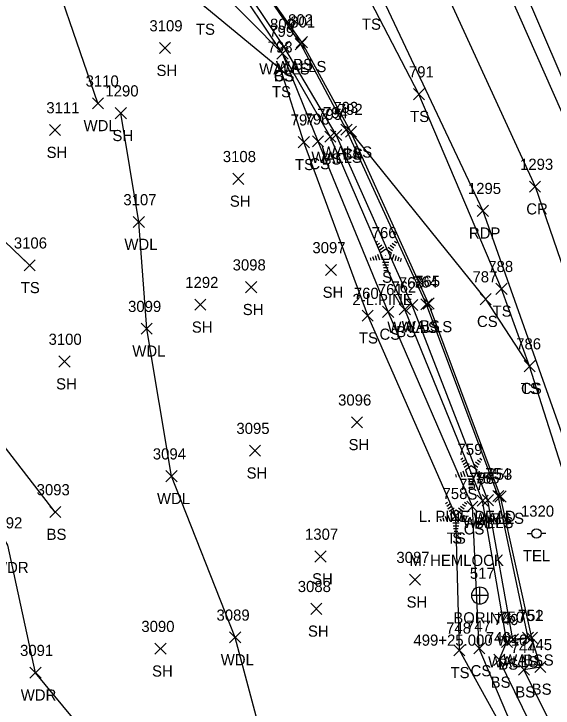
# Model space of a CAD drawing. Extents: x 1509053 to 1511576, y 400838 to 402572.
# Drawn here: x 1509663.6 to 1509760.3, y 401714.2 to 401838.7 of the extents above; entities that cross this region are included whole.
import ezdxf

# ---------------------------------------------------------------- set-up
doc = ezdxf.new("R2010")
doc.units = 0
for name, color, linetype in [('G_A', 7, 'Continuous'), ('G_C', 7, 'Continuous'), ('G_I', 7, 'Continuous'), ('GA_P', 7, 'Continuous'), ('L_A', 7, 'Continuous'), ('L_C', 7, 'Continuous'), ('L_I', 7, 'Continuous'), ('L_TIC', 7, 'Continuous'), ('LAWA', 7, 'Continuous'), ('LELB', 7, 'Continuous'), ('LTC', 7, 'Continuous'), ('LWS', 7, 'Continuous'), ('P_A', 7, 'Continuous'), ('P_I', 7, 'Continuous'), ('P_TIC', 7, 'Continuous'), ('PET', 7, 'Continuous'), ('PRC', 7, 'Continuous'), ('RGR', 7, 'Continuous'), ('U_A', 7, 'Continuous'), ('U_I', 7, 'Continuous'), ('UP', 7, 'Continuous')]:
    doc.layers.add(name, color=color, linetype=linetype)

msp = doc.modelspace()

# ---------------------------------------------------------------- linework, layer by layer
at = {"layer": 'GA_P'}
for p, q in [((1509747.19, 401734.4), (1509747.19, 401735.9)), ((1509747.19, 401734.4), (1509745.69, 401734.4)), ((1509748.69, 401734.4), (1509747.19, 401734.4)), ((1509747.19, 401732.9), (1509747.19, 401734.4))]:
    msp.add_line(p, q, dxfattribs=at)
for start, end in [(90, 180), (0, 90), (180, 270), (270, 0)]:
    msp.add_arc((1509747.19, 401734.4), 1.5, start, end, dxfattribs=at)
at = {"layer": 'L_TIC'}
for points in [[(1509714.05, 401832.27), (1509716.05, 401834.27)], [(1509716.05, 401832.27), (1509714.05, 401834.27)], [(1509714.24, 401832.65), (1509716.24, 401834.65)], [(1509716.24, 401832.65), (1509714.24, 401834.65)], [(1509689.68, 401831.58), (1509691.68, 401833.58)], [(1509691.68, 401831.58), (1509689.68, 401833.58)], [(1509711.05, 401831.85), (1509713.05, 401833.85)], [(1509713.05, 401831.85), (1509711.05, 401833.85)], [(1509710.77, 401830.6), (1509712.77, 401832.6)], [(1509712.77, 401830.6), (1509710.77, 401832.6)], [(1509710.77, 401830.6), (1509712.77, 401832.6)], [(1509712.77, 401830.6), (1509710.77, 401832.6)], [(1509710.48, 401827.76), (1509712.48, 401829.76)], [(1509712.48, 401827.76), (1509710.48, 401829.76)], [(1509735.27, 401823.32), (1509737.27, 401825.32)], [(1509737.27, 401823.32), (1509735.27, 401825.32)], [(1509677.66, 401821.68), (1509679.66, 401823.68)], [(1509679.66, 401821.68), (1509677.66, 401823.68)], [(1509681.78, 401819.91), (1509683.78, 401821.91)], [(1509683.78, 401819.91), (1509681.78, 401821.91)], [(1509669.96, 401816.88), (1509671.96, 401818.88)], [(1509671.96, 401816.88), (1509669.96, 401818.88)], [(1509720.41, 401816), (1509722.41, 401818)], [(1509722.41, 401816), (1509720.41, 401818)], [(1509722.26, 401816.94), (1509724.26, 401818.94)], [(1509724.26, 401816.94), (1509722.26, 401818.94)], [(1509723.07, 401816.58), (1509725.07, 401818.58)], [(1509725.07, 401816.58), (1509723.07, 401818.58)], [(1509723.07, 401816.58), (1509725.07, 401818.58)], [(1509725.07, 401816.58), (1509723.07, 401818.58)], [(1509714.61, 401814.7), (1509716.61, 401816.7)], [(1509716.61, 401814.7), (1509714.61, 401816.7)], [(1509717.16, 401814.85), (1509719.16, 401816.85)], [(1509719.16, 401814.85), (1509717.16, 401816.85)], [(1509719.36, 401815.7), (1509721.36, 401817.7)], [(1509721.36, 401815.7), (1509719.36, 401817.7)], [(1509702.84, 401808.13), (1509704.84, 401810.13)], [(1509704.84, 401808.13), (1509702.84, 401810.13)], [(1509685, 401800.39), (1509687, 401802.39)], [(1509687, 401800.39), (1509685, 401802.39)], [(1509665.4, 401792.63), (1509667.4, 401794.63)], [(1509667.4, 401792.63), (1509665.4, 401794.63)], [(1509719.49, 401791.79), (1509721.49, 401793.79)], [(1509721.49, 401791.79), (1509719.49, 401793.79)], [(1509705.16, 401788.7), (1509707.16, 401790.7)], [(1509707.16, 401788.7), (1509705.16, 401790.7)], [(1509750.07, 401788.41), (1509752.07, 401790.41)], [(1509752.07, 401788.41), (1509750.07, 401790.41)], [(1509747.24, 401786.56), (1509749.24, 401788.56)], [(1509749.24, 401786.56), (1509747.24, 401788.56)], [(1509696.02, 401785.55), (1509698.02, 401787.55)], [(1509698.02, 401785.55), (1509696.02, 401787.55)], [(1509732.73, 401784.72), (1509734.73, 401786.72)], [(1509734.73, 401784.72), (1509732.73, 401786.72)], [(1509734.06, 401785.49), (1509736.06, 401787.49)], [(1509736.06, 401785.49), (1509734.06, 401787.49)], [(1509736.62, 401785.62), (1509738.62, 401787.62)], [(1509738.62, 401785.62), (1509736.62, 401787.62)], [(1509737, 401785.77), (1509739, 401787.77)], [(1509739, 401785.77), (1509737, 401787.77)], [(1509726.08, 401783.6), (1509728.08, 401785.6)], [(1509728.08, 401783.6), (1509726.08, 401785.6)], [(1509729.75, 401784.27), (1509731.75, 401786.27)], [(1509731.75, 401784.27), (1509729.75, 401786.27)], [(1509686.42, 401781.25), (1509688.42, 401783.25)], [(1509688.42, 401781.25), (1509686.42, 401783.25)], [(1509671.66, 401775.36), (1509673.66, 401777.36)], [(1509673.66, 401775.36), (1509671.66, 401777.36)], [(1509755.13, 401774.54), (1509757.13, 401776.54)], [(1509757.13, 401774.54), (1509755.13, 401776.54)], [(1509755.13, 401774.54), (1509757.13, 401776.54)], [(1509757.13, 401774.54), (1509755.13, 401776.54)], [(1509724.15, 401764.47), (1509726.15, 401766.47)], [(1509726.15, 401764.47), (1509724.15, 401766.47)], [(1509705.85, 401759.38), (1509707.85, 401761.38)], [(1509707.85, 401759.38), (1509705.85, 401761.38)], [(1509690.85, 401754.8), (1509692.85, 401756.8)], [(1509692.85, 401754.8), (1509690.85, 401756.8)], [(1509749.51, 401751.25), (1509751.51, 401753.25)], [(1509751.51, 401751.25), (1509749.51, 401753.25)], [(1509749.91, 401751.16), (1509751.91, 401753.16)], [(1509751.91, 401751.16), (1509749.91, 401753.16)], [(1509746.7, 401750.42), (1509748.7, 401752.42)], [(1509748.7, 401750.42), (1509746.7, 401752.42)], [(1509747.62, 401750.49), (1509749.62, 401752.49)], [(1509749.62, 401750.49), (1509747.62, 401752.49)], [(1509744.86, 401749.35), (1509746.86, 401751.35)], [(1509746.86, 401749.35), (1509744.86, 401751.35)], [(1509670, 401748.38), (1509672, 401750.38)], [(1509672, 401748.38), (1509670, 401750.38)], [(1509741.86, 401747.7), (1509743.86, 401749.7)], [(1509743.86, 401747.7), (1509741.86, 401749.7)], [(1509717.59, 401740.4), (1509719.59, 401742.4)], [(1509719.59, 401740.4), (1509717.59, 401742.4)], [(1509734.56, 401736.24), (1509736.56, 401738.24)], [(1509736.56, 401736.24), (1509734.56, 401738.24)], [(1509716.86, 401731.02), (1509718.86, 401733.02)], [(1509718.86, 401731.02), (1509716.86, 401733.02)], [(1509702.28, 401725.89), (1509704.28, 401727.89)], [(1509704.28, 401725.89), (1509702.28, 401727.89)], [(1509751.06, 401725.1), (1509753.06, 401727.1)], [(1509753.06, 401725.1), (1509751.06, 401727.1)], [(1509752.13, 401725.52), (1509754.13, 401727.52)], [(1509754.13, 401725.52), (1509752.13, 401727.52)], [(1509754.84, 401725.84), (1509756.84, 401727.84)], [(1509756.84, 401725.84), (1509754.84, 401727.84)], [(1509755.54, 401725.82), (1509757.54, 401727.82)], [(1509757.54, 401725.82), (1509755.54, 401727.82)], [(1509688.88, 401723.86), (1509690.88, 401725.86)], [(1509690.88, 401723.86), (1509688.88, 401725.86)], [(1509746.09, 401723.92), (1509748.09, 401725.92)], [(1509748.09, 401723.92), (1509746.09, 401725.92)], [(1509742.52, 401723.58), (1509744.52, 401725.58)], [(1509744.52, 401723.58), (1509742.52, 401725.58)], [(1509749.68, 401721.86), (1509751.68, 401723.86)], [(1509751.68, 401721.86), (1509749.68, 401723.86)], [(1509754.11, 401720.11), (1509756.11, 401722.11)], [(1509756.11, 401720.11), (1509754.11, 401722.11)], [(1509757.06, 401720.61), (1509759.06, 401722.61)], [(1509759.06, 401720.61), (1509757.06, 401722.61)], [(1509666.45, 401719.56), (1509668.45, 401721.56)], [(1509668.45, 401719.56), (1509666.45, 401721.56)]]:
    msp.add_lwpolyline(points, dxfattribs=at)
at = {"layer": 'LAWA'}
for points in [[(1509638.88, 401488.13), (1509666.35, 401492.77), (1509693.47, 401489.31), (1509706.73, 401489.66), (1509714.33, 401510.79), (1509715.13, 401545.88), (1509713.34, 401580.23), (1509712.38, 401615.78), (1509710.87, 401643.63), (1509696.77, 401674.88), (1509690.26, 401693.05), (1509667.45, 401720.56), (1509662.48, 401743.44), (1509649.82, 401764.29), (1509628.65, 401784.18), (1509611.29, 401798.2), (1509592.85, 401815.68), (1509576.11, 401831.25), (1509568.72, 401841.78), (1509569.85, 401855.18), (1509582.24, 401868.06), (1509599.14, 401876.59), (1509619.4, 401883.23)], [(1509678.66, 401822.68), (1509667.93, 401853.86)], [(1509686, 401801.39), (1509682.78, 401820.91)], [(1509711.02, 401698), (1509703.28, 401726.89), (1509691.85, 401755.8), (1509687.42, 401782.25), (1509686, 401801.39)]]:
    msp.add_lwpolyline(points, dxfattribs=at)
at = {"layer": 'LELB'}
for points in [[(1509773.23, 401624.44), (1509773.26, 401652.55), (1509769.07, 401681.27), (1509762.8, 401705.65), (1509755.11, 401721.11), (1509758.06, 401721.61), (1509756.54, 401726.82), (1509750.91, 401752.16), (1509738, 401786.77), (1509724.07, 401817.58), (1509715.24, 401833.65), (1509705.02, 401848.12), (1509687.56, 401874.43), (1509682.95, 401881.5), (1509682.01, 401883.09), (1509678.34, 401883.46), (1509668.76, 401883.33)], [(1509755.23, 401531.03), (1509759.29, 401552.77), (1509765.02, 401573.72), (1509768.89, 401600.17), (1509768.39, 401615.04), (1509767.46, 401619.69), (1509766.78, 401624.18), (1509765.92, 401630.49), (1509768.74, 401634.34), (1509769.29, 401651.82), (1509765.23, 401681.64), (1509759.03, 401705.77), (1509750.68, 401722.86), (1509752.06, 401726.1), (1509747.7, 401751.42), (1509733.73, 401785.72), (1509720.36, 401816.7), (1509711.77, 401831.6), (1509702.38, 401845.68), (1509682.87, 401874.27), (1509678.54, 401880.58), (1509678.34, 401883.46)], [(1509731.39, 401479.41), (1509744.85, 401504.05), (1509748.4, 401505.28), (1509750.98, 401532.46), (1509751.98, 401551.59), (1509758.3, 401575), (1509758.92, 401604.42), (1509759.53, 401620.15), (1509759.5, 401642.39), (1509763.87, 401657.52), (1509763.43, 401681.67), (1509755.33, 401705.43), (1509747.09, 401724.92), (1509745.86, 401750.35), (1509730.75, 401785.27), (1509718.16, 401815.85), (1509711.77, 401831.6), (1509699.84, 401843.77), (1509676.05, 401879.71), (1509667.99, 401880.98)], [(1509763.87, 401657.52), (1509759.59, 401677.55), (1509753.4, 401706.7), (1509743.52, 401724.58), (1509742.86, 401748.7), (1509727.08, 401784.6), (1509715.61, 401815.7), (1509711.48, 401828.76), (1509697.83, 401839.96), (1509674.9, 401875.7), (1509667.99, 401880.98)], [(1509747.77, 401416.63), (1509750.21, 401428.63), (1509752.14, 401443.01), (1509750.46, 401466.15), (1509760.48, 401503.51), (1509765.49, 401528.65), (1509770.9, 401551.56), (1509776.3, 401572.59), (1509780.48, 401596.32), (1509778.93, 401605.73), (1509782.51, 401627.45), (1509784.95, 401662.22), (1509781.8, 401680.58), (1509772.99, 401719.38), (1509769.17, 401721), (1509769.65, 401723.75), (1509771.91, 401724.32), (1509762.66, 401754.93), (1509756.13, 401775.54), (1509751.07, 401789.41), (1509736.27, 401824.32), (1509727.62, 401840.87), (1509712.26, 401861.01), (1509694.01, 401878.11)], [(1509666.4, 401793.63), (1509650.07, 401809.23), (1509603.01, 401836.26), (1509576.11, 401831.25)], [(1509756.13, 401775.54), (1509748.24, 401787.56), (1509724.07, 401817.58)], [(1509671, 401749.38), (1509656.53, 401768), (1509641.1, 401782.64)], [(1509756.54, 401726.82), (1509752.06, 401726.1)]]:
    msp.add_lwpolyline(points, dxfattribs=at)
at = {"layer": 'LTC'}
for p, q in [((1509728.45, 401797.69), (1509728.81, 401797.95)), ((1509731.85, 401797.93), (1509732.27, 401797.63)), ((1509728.66, 401797.23), (1509729.19, 401797.61)), ((1509728.87, 401796.76), (1509729.58, 401797.27)), ((1509729.08, 401796.3), (1509729.96, 401796.93)), ((1509729.31, 401795.84), (1509730.32, 401796.58)), ((1509730.32, 401796.58), (1509731.31, 401795.85)), ((1509730.74, 401796.89), (1509731.55, 401796.3)), ((1509731.11, 401797.24), (1509731.79, 401796.74)), ((1509731.48, 401797.59), (1509732.03, 401797.19)), ((1509728.4, 401795.41), (1509728.67, 401794.57)), ((1509728.85, 401795.62), (1509729.18, 401794.6)), ((1509729.31, 401795.84), (1509729.69, 401794.65)), ((1509731.31, 401795.85), (1509730.92, 401794.65)), ((1509731.75, 401795.58), (1509731.41, 401794.54)), ((1509732.2, 401795.33), (1509731.91, 401794.45)), ((1509727.49, 401794.97), (1509727.64, 401794.5)), ((1509727.94, 401795.19), (1509728.15, 401794.54)), ((1509730.92, 401794.65), (1509729.69, 401794.65)), ((1509730.89, 401794.15), (1509729.74, 401794.15)), ((1509732.64, 401795.08), (1509732.4, 401794.35)), ((1509733.09, 401794.83), (1509732.9, 401794.26)), ((1509730.8, 401793.65), (1509729.81, 401793.65)), ((1509730.72, 401793.15), (1509729.89, 401793.15)), ((1509730.63, 401792.65), (1509729.96, 401792.65)), ((1509743.77, 401758.82), (1509744.12, 401759.08)), ((1509743.98, 401758.35), (1509744.51, 401758.74)), ((1509744.19, 401757.89), (1509744.89, 401758.4)), ((1509744.4, 401757.42), (1509745.27, 401758.06)), ((1509746.05, 401758.01), (1509746.86, 401757.42)), ((1509746.42, 401758.36), (1509747.1, 401757.87)), ((1509746.79, 401758.71), (1509747.34, 401758.31)), ((1509747.17, 401759.06), (1509747.58, 401758.75)), ((1509744.17, 401756.75), (1509744.5, 401755.73)), ((1509744.62, 401756.97), (1509745.63, 401757.7)), ((1509744.62, 401756.97), (1509745.01, 401755.77)), ((1509745.63, 401757.7), (1509746.63, 401756.98)), ((1509746.63, 401756.98), (1509746.24, 401755.77)), ((1509742.8, 401756.1), (1509742.95, 401755.63)), ((1509743.25, 401756.31), (1509743.47, 401755.66)), ((1509743.71, 401756.53), (1509743.98, 401755.69)), ((1509746.24, 401755.77), (1509745.01, 401755.77)), ((1509747.07, 401756.7), (1509746.73, 401755.66)), ((1509747.51, 401756.45), (1509747.22, 401755.57)), ((1509747.96, 401756.2), (1509747.72, 401755.47)), ((1509748.4, 401755.95), (1509748.21, 401755.38)), ((1509746.2, 401755.27), (1509745.05, 401755.27)), ((1509746.12, 401754.77), (1509745.13, 401754.77)), ((1509746.03, 401754.27), (1509745.2, 401754.27)), ((1509745.95, 401753.77), (1509745.27, 401753.77)), ((1509741.05, 401750.9), (1509741.41, 401751.16)), ((1509741.26, 401750.44), (1509741.79, 401750.82)), ((1509744.08, 401750.8), (1509744.63, 401750.4)), ((1509744.45, 401751.15), (1509744.87, 401750.84)), ((1509741.47, 401749.97), (1509742.18, 401750.48)), ((1509741.68, 401749.51), (1509742.56, 401750.15)), ((1509741.91, 401749.05), (1509742.92, 401749.79)), ((1509742.92, 401749.79), (1509743.92, 401749.06)), ((1509743.34, 401750.1), (1509744.15, 401749.51)), ((1509743.71, 401750.45), (1509744.39, 401749.95)), ((1509740.09, 401748.18), (1509740.24, 401747.72)), ((1509740.54, 401748.4), (1509740.75, 401747.75)), ((1509741, 401748.62), (1509741.27, 401747.78)), ((1509741.45, 401748.83), (1509741.78, 401747.81)), ((1509741.91, 401749.05), (1509742.3, 401747.86)), ((1509743.92, 401749.06), (1509743.53, 401747.86)), ((1509744.35, 401748.79), (1509744.02, 401747.75)), ((1509744.8, 401748.54), (1509744.51, 401747.66)), ((1509745.24, 401748.29), (1509745.01, 401747.56)), ((1509745.69, 401748.04), (1509745.5, 401747.47)), ((1509743.53, 401747.86), (1509742.3, 401747.86)), ((1509743.49, 401747.36), (1509742.34, 401747.36)), ((1509743.4, 401746.86), (1509742.42, 401746.86)), ((1509743.32, 401746.36), (1509742.49, 401746.36)), ((1509743.24, 401745.86), (1509742.56, 401745.86))]:
    msp.add_line(p, q, dxfattribs=at)
at = {"layer": 'LWS'}
for points in [[(1509753.13, 401726.52), (1509748.62, 401751.49), (1509735.06, 401786.49), (1509721.41, 401817), (1509712.05, 401832.85), (1509703.08, 401846.24), (1509685.01, 401872.29), (1509679.34, 401882.1), (1509682.12, 401881.75)], [(1509755.84, 401726.84), (1509750.51, 401752.25), (1509737.62, 401786.62), (1509723.26, 401817.94), (1509715.05, 401833.27), (1509705.08, 401847.91), (1509687.93, 401873.49), (1509682.12, 401881.75)], [(1509755.84, 401726.84), (1509753.13, 401726.52)]]:
    msp.add_lwpolyline(points, dxfattribs=at)
at = {"layer": 'P_TIC'}
for points in [[(1509756.1, 401806.74), (1509758.1, 401808.74)], [(1509758.1, 401806.74), (1509756.1, 401808.74)], [(1509746.74, 401802.4), (1509748.74, 401804.4)], [(1509748.74, 401802.4), (1509746.74, 401804.4)]]:
    msp.add_lwpolyline(points, dxfattribs=at)
at = {"layer": 'PET'}
for points in [[(1509715.31, 401901.72), (1509745.32, 401858.52), (1509766.29, 401811.16), (1509783.05, 401763.87), (1509797.74, 401715.42), (1509812.83, 401666.24)], [(1509690.27, 401895.46), (1509701.64, 401882.87), (1509726.68, 401848.01), (1509747.74, 401803.41), (1509763.81, 401758.01), (1509775.46, 401713.07), (1509786.05, 401661.7), (1509787.8, 401644.85), (1509788.16, 401621.99), (1509786.62, 401596.26), (1509780.1, 401566.45), (1509768.35, 401517.81), (1509758.18, 401467.69), (1509749.79, 401418)]]:
    msp.add_lwpolyline(points, dxfattribs=at)
at = {"layer": 'PRC'}
msp.add_lwpolyline([(1509707.24, 401894.16), (1509736.22, 401853.25), (1509757.1, 401807.74), (1509773.38, 401760.44), (1509787.69, 401712.52), (1509798.93, 401663.6)], dxfattribs=at)
at = {"layer": 'RGR'}
msp.add_lwpolyline([(1509718.97, 401902.89), (1509748.05, 401859.65), (1509768.47, 401812.01), (1509784.69, 401764.48), (1509800.96, 401717.11), (1509817.16, 401667.22)], dxfattribs=at)
at = {"layer": 'UP'}
for p, q in [((1509755.69, 401745.54), (1509756.52, 401745.54)), ((1509757.35, 401745.54), (1509757.35, 401745.54)), ((1509759.02, 401745.54), (1509758.19, 401745.54)), ((1509758.19, 401745.54), (1509758.19, 401745.54)), ((1509759.02, 401745.54), (1509759.02, 401745.54))]:
    msp.add_line(p, q, dxfattribs=at)
msp.add_circle((1509757.35, 401745.54), 0.833, dxfattribs=at)

# ---------------------------------------------------------------- texts
at = {"layer": 'G_A'}
msp.add_text('BORING', height=2, dxfattribs=at).set_placement((1509742.43, 401729.4))
at = {"layer": 'G_C'}
msp.add_text('499+25.000 W10', height=2, dxfattribs=at).set_placement((1509735.28, 401725.4))
at = {"layer": 'G_I'}
msp.add_text('517', height=2, dxfattribs=at).set_placement((1509745.4, 401737.4))
at = {"layer": 'L_A'}
for s, p in [('TS', (1509726.03, 401835.87)), ('TS', (1509696.24, 401834.96)), ('WALLS', (1509710.59, 401828.27)), ('BS', (1509713.68, 401828.65)), ('SH', (1509689.17, 401827.58)), ('WALLS', (1509707.6, 401827.85)), ('CS', (1509710.21, 401826.6)), ('BS', (1509710.21, 401826.6)), ('TS', (1509709.89, 401823.76)), ('TS', (1509734.68, 401819.32)), ('WDL', (1509676.08, 401817.68)), ('SH', (1509681.26, 401815.9)), ('SH', (1509669.45, 401812.88)), ('WALLS', (1509716.96, 401812)), ('WALLS', (1509718.8, 401812.94)), ('CS', (1509722.51, 401812.58)), ('BS', (1509722.51, 401812.58)), ('CS', (1509716.6, 401810.85)), ('BS', (1509718.8, 401811.7)), ('TS', (1509714.02, 401810.7)), ('SH', (1509702.33, 401804.13)), ('WDL', (1509683.41, 401796.39)), ('S', (1509729.64, 401790.49)), ('TS', (1509664.81, 401788.63)), ('SH', (1509718.98, 401787.79)), ('SH', (1509704.65, 401784.7)), ('TS', (1509749.48, 401784.41)), ('CS', (1509746.68, 401782.56)), ('SH', (1509695.51, 401781.55)), ('WALLS', (1509730.6, 401781.49)), ('WALLS', (1509733.17, 401781.62)), ('BS', (1509736.44, 401781.77)), ('TS', (1509725.49, 401779.6)), ('CS', (1509729.19, 401780.27)), ('BS', (1509732.17, 401780.72)), ('WDL', (1509684.83, 401777.25)), ('SH', (1509671.15, 401771.36)), ('TS', (1509754.54, 401770.54)), ('CS', (1509754.58, 401770.54)), ('SH', (1509723.64, 401760.47)), ('SH', (1509705.34, 401755.38)), ('S', (1509744.96, 401751.61)), ('WDL', (1509689.26, 401750.8)), ('WALLS', (1509746.05, 401747.25)), ('WALLS', (1509744.16, 401746.49)), ('BS', (1509746.14, 401746.42)), ('BS', (1509749.35, 401747.16)), ('CS', (1509744.3, 401745.35)), ('BS', (1509669.44, 401744.38)), ('TS', (1509741.27, 401743.7)), ('S', (1509742.25, 401743.7)), ('WDR', (1509659.84, 401738.44)), ('SH', (1509717.08, 401736.4)), ('SH', (1509734.05, 401732.24)), ('SH', (1509716.35, 401727.02)), ('WDL', (1509700.7, 401721.89)), ('WALLS', (1509748.67, 401721.52)), ('BS', (1509750.5, 401721.1)), ('WALLS', (1509751.38, 401721.84)), ('BS', (1509754.98, 401721.82)), ('SH', (1509688.37, 401719.86)), ('CS', (1509745.53, 401719.92)), ('TS', (1509741.93, 401719.58)), ('BS', (1509749.13, 401717.86)), ('BS', (1509753.55, 401716.11)), ('BS', (1509756.5, 401716.61)), ('WDR', (1509664.81, 401715.56))]:
    msp.add_text(s, height=2, dxfattribs=at).set_placement(p)
at = {"layer": 'L_C'}
for s, p in [('2-L.PINE', (1509724.32, 401786.49)), ('L. PINE DEAD', (1509736.24, 401747.61)), ('M. HEMLOCK', (1509734.56, 401739.7))]:
    msp.add_text(s, height=2, dxfattribs=at).set_placement(p)
at = {"layer": 'L_I'}
for s, p in [('800', (1509709.53, 401835.85)), ('802', (1509712.79, 401836.65)), ('801', (1509713.17, 401836.27)), ('3109', (1509687.9, 401835.58)), ('799', (1509709.4, 401834.6)), ('799', (1509709.4, 401834.6)), ('798', (1509709.12, 401831.76)), ('791', (1509734.47, 401827.32)), ('3110', (1509676.45, 401825.68)), ('1290', (1509680, 401823.91)), ('3111', (1509669.4, 401820.88)), ('793', (1509720.9, 401820.94)), ('795', (1509718, 401819.7)), ('794', (1509719.05, 401820)), ('792', (1509721.71, 401820.58)), ('792', (1509721.71, 401820.58)), ('797', (1509713.25, 401818.7)), ('796', (1509715.75, 401818.85)), ('3108', (1509701.07, 401812.13)), ('3107', (1509683.22, 401804.39)), ('766', (1509727.79, 401798.49)), ('3106', (1509663.57, 401796.63)), ('3097', (1509717.15, 401795.79)), ('3098', (1509702.83, 401792.7)), ('788', (1509748.71, 401792.41)), ('764', (1509735.21, 401789.62)), ('765', (1509735.59, 401789.77)), ('787', (1509745.87, 401790.56)), ('1292', (1509694.33, 401789.55)), ('762', (1509731.32, 401788.72)), ('763', (1509732.65, 401789.49)), ('760', (1509724.59, 401787.6)), ('761', (1509728.9, 401788.27)), ('3099', (1509684.07, 401785.25)), ('3100', (1509669.8, 401779.36)), ('786', (1509753.72, 401778.54)), ('786', (1509753.72, 401778.54)), ('3096', (1509721.76, 401768.47)), ('3095', (1509703.51, 401763.38)), ('3094', (1509688.51, 401758.8)), ('759', (1509743.2, 401759.61)), ('754', (1509748.15, 401755.25)), ('753', (1509748.55, 401755.16)), ('756', (1509745.28, 401754.42)), ('755', (1509746.26, 401754.49)), ('3093', (1509667.66, 401752.38)), ('757', (1509743.5, 401753.35)), ('758', (1509740.5, 401751.7)), ('758', (1509740.5, 401751.7)), ('3092', (1509659.14, 401746.44)), ('1307', (1509715.82, 401744.4)), ('3087', (1509732.22, 401740.24)), ('3088', (1509714.52, 401735.02)), ('3089', (1509699.94, 401729.89)), ('751', (1509754.05, 401729.84)), ('752', (1509754.18, 401729.82)), ('749', (1509749.69, 401729.1)), ('750', (1509750.68, 401729.52)), ('3090', (1509686.45, 401727.86)), ('748', (1509741.15, 401727.58)), ('747', (1509744.73, 401727.92)), ('746', (1509748.27, 401725.86)), ('744', (1509752.75, 401724.11)), ('745', (1509755.7, 401724.61)), ('3091', (1509664.68, 401723.56))]:
    msp.add_text(s, height=2, dxfattribs=at).set_placement(p)
at = {"layer": 'LTC'}
for p in [(1509730.2, 401795.59), (1509745.51, 401756.71), (1509742.8, 401748.8)]:
    msp.add_text('.', height=1.04, rotation=270, dxfattribs=at).set_placement(p)
at = {"layer": 'P_A'}
for s, p in [('CR', (1509755.53, 401802.74)), ('RDP', (1509745.23, 401798.41))]:
    msp.add_text(s, height=2, dxfattribs=at).set_placement(p)
at = {"layer": 'P_I'}
for s, p in [('1293', (1509754.41, 401810.74)), ('1295', (1509745.05, 401806.41))]:
    msp.add_text(s, height=2, dxfattribs=at).set_placement(p)
at = {"layer": 'U_A'}
msp.add_text('TEL', height=2, dxfattribs=at).set_placement((1509754.91, 401740.54))
at = {"layer": 'U_I'}
msp.add_text('1320', height=2, dxfattribs=at).set_placement((1509754.57, 401748.54))

doc.saveas('drawing.dxf')
